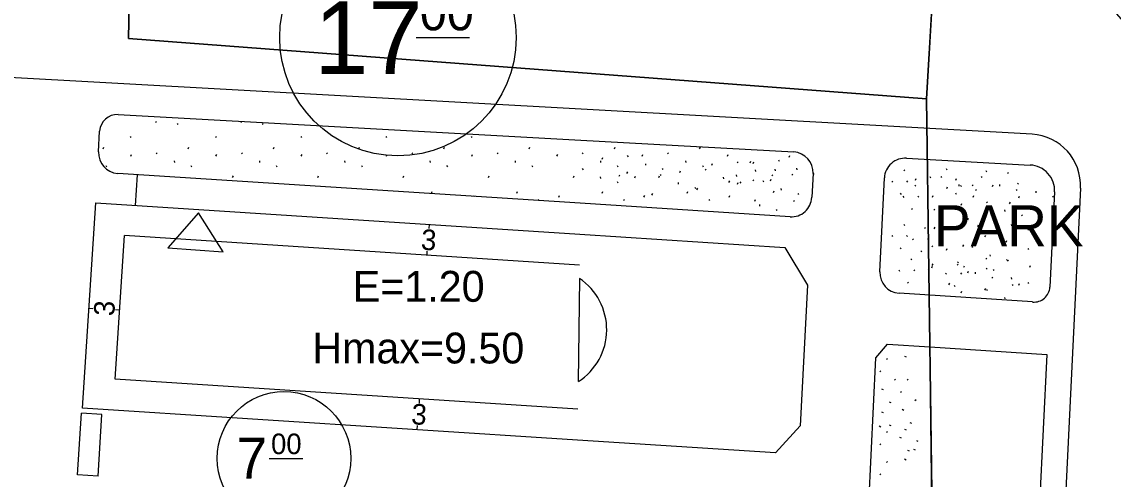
# Model space of a CAD drawing. Extents: x 419396 to 421519, y 4453567 to 4456767.
# Drawn here: x 421210.1 to 421316.3, y 4454782 to 4454826.5 of the extents above; entities that cross this region are included whole.
import ezdxf

# ---------------------------------------------------------------- set-up
doc = ezdxf.new("R2010")
doc.units = 0
for name, color, linetype in [('0_KADASTRO', 7, 'Continuous'), ('Level 16', 7, 'Continuous'), ('Level 20', 7, 'Continuous'), ('Level 28', 7, 'Continuous'), ('Level 29', 7, 'Continuous'), ('Level 30', 7, 'Continuous'), ('Level 32', 7, 'Continuous'), ('Level 41', 7, 'Continuous'), ('Level 5', 7, 'Continuous'), ('Level 53', 7, 'Continuous'), ('Level 58', 7, 'Continuous'), ('Level 59', 7, 'Continuous'), ('Level 62', 7, 'Continuous')]:
    doc.layers.add(name, color=color, linetype=linetype)

msp = doc.modelspace()

# ---------------------------------------------------------------- linework, layer by layer
at = {"layer": '0_KADASTRO'}
for points in [[(421137.98, 4454923.3), (421214.86, 4454919.45), (421262.85, 4454917.05), (421316.7, 4454915.64), (421312.35, 4454909.46), (421306.52, 4454893.75), (421298.93, 4454879.53), (421285.07, 4454880), (421282.36, 4454831.02), (421298.78, 4454830.11), (421298.12, 4454819), (421220.47, 4454824.89), (421221.51, 4454877.03), (421221.57, 4454879.85), (421203.67, 4454880.3), (421204.77, 4454912.41), (421155.31, 4454914.55), (421152.21, 4454911.69), (421151.19, 4454881.63), (421145.39, 4454881.78), (421142.95, 4454883.52), (421140.69, 4454887.48), (421139.91, 4454900.08)], [(421127.23, 4454779.24), (421128.91, 4454801.39), (421131.96, 4454828.83), (421129.84, 4454852.82), (421130.22, 4454865.45), (421131.1, 4454878.14), (421221.51, 4454877.03), (421220.47, 4454824.89), (421298.12, 4454819), (421298.8, 4454768.82), (421229.78, 4454772.84), (421167.18, 4454777.23)], [(421297.3, 4454718.68), (421298.33, 4454743.86), (421298.65, 4454753.52), (421298.8, 4454768.82), (421298.12, 4454819), (421299.79, 4454847.06), (421309.91, 4454834.93), (421332.63, 4454808.99), (421350.71, 4454801.96), (421374.76, 4454802.88), (421400.86, 4454807.28), (421429.39, 4454805.15), (421423.5, 4454722.17), (421393.26, 4454602.31), (421372.96, 4454614.59), (421362.83, 4454633.4), (421361.48, 4454641.58), (421342.8, 4454669.52), (421331.29, 4454695.38), (421310.81, 4454712.23)], [(421297.3, 4454718.68), (421298.33, 4454743.86), (421298.65, 4454753.52), (421298.8, 4454768.82), (421298.12, 4454819), (421299.79, 4454847.06), (421309.91, 4454834.93), (421332.63, 4454808.99), (421350.71, 4454801.96), (421374.76, 4454802.88), (421400.86, 4454807.28), (421429.39, 4454805.15), (421423.5, 4454722.17), (421393.26, 4454602.31), (421372.96, 4454614.59), (421362.83, 4454633.4), (421361.48, 4454641.58), (421342.8, 4454669.52), (421331.29, 4454695.38), (421310.81, 4454712.23)]]:
    msp.add_lwpolyline(points, close=True, dxfattribs=at)
at = {"layer": 'Level 16'}
for p, q in [((421227.29, 4454807.91), (421224.32, 4454804.52)), ((421229.7, 4454804.11), (421227.29, 4454807.91)), ((421224.32, 4454804.52), (421229.7, 4454804.11))]:
    msp.add_line(p, q, dxfattribs=at)
at = {"layer": 'Level 20'}
for p, q in [((421249.72, 4454806.79), (421249.69, 4454806.39)), ((421219.18, 4454791.73), (421220.09, 4454805.7)), ((421264.36, 4454802.84), (421220.09, 4454805.7)), ((421249.53, 4454803.8), (421249.55, 4454804.2)), ((421264.36, 4454802.84), (421264.36, 4454802.84)), ((421264.36, 4454802.84), (421264.36, 4454802.84)), ((421264.36, 4454802.84), (421264.36, 4454802.84)), ((421216.62, 4454798.66), (421217.02, 4454798.63)), ((421219.62, 4454798.46), (421219.22, 4454798.49)), ((421264.21, 4454788.82), (421219.18, 4454791.73)), ((421248.77, 4454789.82), (421248.75, 4454789.42)), ((421264.21, 4454788.82), (421264.21, 4454788.82)), ((421264.21, 4454788.82), (421264.21, 4454788.82)), ((421264.21, 4454788.82), (421264.21, 4454788.82)), ((421248.58, 4454786.83), (421248.6, 4454787.22))]:
    msp.add_line(p, q, dxfattribs=at)
at = {"layer": 'Level 28'}
for p, q in [((421219.48, 4454817.48), (421264.49, 4454814.98)), ((421217.56, 4454813.86), (421217.67, 4454815.86)), ((421264.49, 4454814.98), (421264.49, 4454814.98)), ((421264.49, 4454814.98), (421264.49, 4454814.98)), ((421264.49, 4454814.98), (421264.49, 4454814.98)), ((421264.42, 4454808.85), (421219.43, 4454811.75)), ((421221.32, 4454811.63), (421221.13, 4454808.64)), ((421215.99, 4454788.92), (421217.29, 4454808.88)), ((421264.42, 4454808.85), (421264.42, 4454808.85)), ((421264.42, 4454808.85), (421264.42, 4454808.85)), ((421264.42, 4454808.85), (421264.42, 4454808.85))]:
    msp.add_line(p, q, dxfattribs=at)
for centre, radius, start, end in [((421219.38, 4454815.77), 1.71, 86.8311, 176.8311), ((421219.56, 4454813.75), 2, 176.8311, 266.3111)]:
    msp.add_arc(centre, radius, start, end, dxfattribs=at)
at = {"layer": 'Level 29'}
for p, q in [((421217.29, 4454808.88), (421264.39, 4454805.85)), ((421264.39, 4454805.85), (421264.39, 4454805.85)), ((421264.39, 4454805.85), (421264.39, 4454805.85)), ((421264.39, 4454805.85), (421264.39, 4454805.85)), ((421298.45, 4454794.88), (421309.82, 4454794.15)), ((421309.82, 4454794.15), (421306.57, 4454727.03)), ((421264.18, 4454785.82), (421215.99, 4454788.92)), ((421264.18, 4454785.82), (421264.18, 4454785.82)), ((421264.18, 4454785.82), (421264.18, 4454785.82)), ((421264.18, 4454785.82), (421264.18, 4454785.82))]:
    msp.add_line(p, q, dxfattribs=at)
at = {"layer": 'Level 32'}
msp.add_lwpolyline([(421264.35, 4454801.54), (421264.24, 4454791.5)], dxfattribs=at)
msp.add_arc((421261.01, 4454796.56), 6, 302.6363, 56.1689, dxfattribs=at)
at = {"layer": 'Level 41'}
for p, q in [((421223.1, 4454816.8), (421223.17, 4454816.69)), ((421225.2, 4454816.61), (421225.27, 4454816.5)), ((421231.39, 4454816.8), (421231.46, 4454816.69)), ((421233.49, 4454816.61), (421233.56, 4454816.5)), ((421220.64, 4454815.35), (421220.71, 4454815.24)), ((421228.93, 4454815.35), (421229, 4454815.24)), ((421237.23, 4454815.35), (421237.3, 4454815.24)), ((421245.52, 4454815.35), (421245.59, 4454815.24)), ((421253.81, 4454815.35), (421253.88, 4454815.24)), ((421218, 4454814.15), (421218.07, 4454814.31)), ((421220.7, 4454813.43), (421220.77, 4454813.59)), ((421223.16, 4454813.77), (421223.23, 4454813.66)), ((421226.29, 4454814.15), (421226.36, 4454814.31)), ((421228.99, 4454813.43), (421229.06, 4454813.59)), ((421231.46, 4454813.77), (421231.53, 4454813.66)), ((421234.59, 4454814.15), (421234.66, 4454814.31)), ((421237.28, 4454813.43), (421237.36, 4454813.59)), ((421239.75, 4454813.77), (421239.82, 4454813.66)), ((421242.88, 4454814.15), (421242.95, 4454814.31)), ((421245.58, 4454813.43), (421245.65, 4454813.59)), ((421248.04, 4454813.77), (421248.11, 4454813.66)), ((421251.17, 4454814.15), (421251.24, 4454814.31)), ((421253.87, 4454813.43), (421253.94, 4454813.59)), ((421256.34, 4454813.77), (421256.41, 4454813.66)), ((421259.46, 4454814.15), (421259.54, 4454814.31)), ((421262.16, 4454813.43), (421262.24, 4454813.59)), ((421264.63, 4454813.77), (421264.7, 4454813.66)), ((421267.76, 4454814.15), (421267.83, 4454814.31)), ((421269.01, 4454813.49), (421269.08, 4454813.38)), ((421270.46, 4454813.43), (421270.53, 4454813.59)), ((421272.92, 4454813.77), (421272.99, 4454813.66)), ((421276.05, 4454814.15), (421276.12, 4454814.31)), ((421278.75, 4454813.43), (421278.82, 4454813.59)), ((421284.76, 4454813.33), (421284.83, 4454813.49)), ((421218.26, 4454812.51), (421218.33, 4454812.4)), ((421224.92, 4454812.98), (421224.94, 4454812.82)), ((421226.55, 4454812.51), (421226.62, 4454812.4)), ((421233.21, 4454812.98), (421233.23, 4454812.82)), ((421234.84, 4454812.51), (421234.91, 4454812.4)), ((421241.51, 4454812.98), (421241.53, 4454812.82)), ((421243.14, 4454812.51), (421243.21, 4454812.4)), ((421249.8, 4454812.98), (421249.82, 4454812.82)), ((421251.43, 4454812.51), (421251.5, 4454812.4)), ((421258.09, 4454812.98), (421258.11, 4454812.82)), ((421259.72, 4454812.51), (421259.79, 4454812.4)), ((421266.39, 4454812.98), (421266.4, 4454812.82)), ((421266.55, 4454813.15), (421266.62, 4454813.31)), ((421268.02, 4454812.51), (421268.09, 4454812.4)), ((421270.77, 4454812.7), (421270.79, 4454812.54)), ((421274.68, 4454812.98), (421274.7, 4454812.82)), ((421276.31, 4454812.51), (421276.38, 4454812.4)), ((421277.23, 4454812.55), (421277.3, 4454812.71)), ((421279.69, 4454812.89), (421279.76, 4454812.79)), ((421280.97, 4454812.79), (421281.04, 4454812.95)), ((421281.25, 4454812.71), (421281.32, 4454812.87)), ((421283.72, 4454813.06), (421283.79, 4454812.95)), ((421230.61, 4454811.37), (421230.68, 4454811.53)), ((421238.9, 4454811.37), (421238.97, 4454811.53)), ((421247.19, 4454811.37), (421247.27, 4454811.53)), ((421255.49, 4454811.37), (421255.56, 4454811.53)), ((421263.78, 4454811.37), (421263.85, 4454811.53)), ((421264.63, 4454812.22), (421264.7, 4454812.11)), ((421266.38, 4454811.43), (421266.4, 4454811.27)), ((421268.22, 4454811.47), (421268.29, 4454811.63)), ((421268.98, 4454811.75), (421269.05, 4454811.91)), ((421269.73, 4454811.31), (421269.81, 4454811.47)), ((421272.07, 4454811.37), (421272.14, 4454811.53)), ((421272.2, 4454811.66), (421272.27, 4454811.55)), ((421272.4, 4454812.23), (421272.47, 4454812.12)), ((421274.12, 4454811.83), (421274.19, 4454811.99)), ((421276.58, 4454812.18), (421276.65, 4454812.07)), ((421278.34, 4454811.39), (421278.36, 4454811.23)), ((421279.6, 4454811.61), (421279.62, 4454811.45)), ((421281.45, 4454812.1), (421281.47, 4454811.94)), ((421283.08, 4454811.63), (421283.15, 4454811.53)), ((421283.38, 4454812.16), (421283.4, 4454812)), ((421285.01, 4454811.69), (421285.08, 4454811.58)), ((421285.47, 4454812.27), (421285.49, 4454812.11)), ((421287.1, 4454811.8), (421287.17, 4454811.69)), ((421295.91, 4454812.09), (421295.98, 4454811.99)), ((421297.04, 4454811.11), (421297.11, 4454811.27)), ((421298.43, 4454811.44), (421298.5, 4454811.33)), ((421299.5, 4454811.46), (421299.57, 4454811.35)), ((421300.03, 4454812.22), (421300.1, 4454812.11)), ((421300.98, 4454811.11), (421301.05, 4454811.27)), ((421303.45, 4454811.46), (421303.52, 4454811.35)), ((421303.89, 4454812.03), (421303.96, 4454811.92)), ((421305.99, 4454811.84), (421306.06, 4454811.73)), ((421268.01, 4454810.96), (421268.08, 4454810.85)), ((421273.96, 4454810.87), (421273.97, 4454810.71)), ((421275.59, 4454810.4), (421275.66, 4454810.29)), ((421275.79, 4454810.16), (421275.86, 4454810.32)), ((421278.9, 4454810.87), (421278.97, 4454811.03)), ((421279.74, 4454810.72), (421279.81, 4454810.88)), ((421279.97, 4454810.92), (421280.04, 4454810.81)), ((421281.23, 4454811.14), (421281.3, 4454811.04)), ((421282.2, 4454811.06), (421282.27, 4454810.95)), ((421282.93, 4454811.04), (421283, 4454811.2)), ((421283.96, 4454810.27), (421283.98, 4454810.11)), ((421294.74, 4454811), (421294.81, 4454810.89)), ((421296.19, 4454811.02), (421296.27, 4454810.91)), ((421297, 4454810.62), (421297.07, 4454810.51)), ((421300.09, 4454810.3), (421300.16, 4454810.46)), ((421301.26, 4454810.67), (421301.28, 4454810.51)), ((421301.44, 4454810.58), (421301.51, 4454810.47)), ((421302.55, 4454810.64), (421302.62, 4454810.53)), ((421302.89, 4454810.2), (421302.96, 4454810.09)), ((421304.53, 4454810.48), (421304.6, 4454810.64)), ((421305.21, 4454810.67), (421305.22, 4454810.51)), ((421306.84, 4454810.2), (421306.91, 4454810.09)), ((421306.99, 4454810.82), (421307.07, 4454810.71)), ((421249.97, 4454809.84), (421250.04, 4454810)), ((421254.09, 4454809.52), (421254.12, 4454809.59)), ((421258.26, 4454809.84), (421258.33, 4454810)), ((421260.35, 4454809.22), (421260.42, 4454809.11)), ((421262.34, 4454809.43), (421262.41, 4454809.59)), ((421266.55, 4454809.84), (421266.62, 4454810)), ((421268.65, 4454809.22), (421268.72, 4454809.11)), ((421270.63, 4454809.43), (421270.71, 4454809.59)), ((421271.41, 4454809.64), (421271.48, 4454809.8)), ((421274.84, 4454809.84), (421274.91, 4454810)), ((421276.94, 4454809.22), (421277.01, 4454809.11)), ((421278.93, 4454809.43), (421279, 4454809.59)), ((421281.41, 4454809.04), (421281.48, 4454809.2)), ((421283.23, 4454809.9), (421283.3, 4454810.06)), ((421285.18, 4454809.13), (421285.25, 4454809.03)), ((421285.59, 4454809.8), (421285.66, 4454809.69)), ((421295.56, 4454809.82), (421295.64, 4454809.71)), ((421295.83, 4454809.53), (421295.9, 4454809.42)), ((421297.29, 4454809.54), (421297.36, 4454809.43)), ((421298.71, 4454809.44), (421298.78, 4454809.6)), ((421300.95, 4454809.86), (421301.02, 4454809.75)), ((421302.66, 4454809.44), (421302.73, 4454809.6)), ((421307.09, 4454809.38), (421307.16, 4454809.54)), ((421308.75, 4454810.03), (421308.77, 4454809.87)), ((421310.38, 4454809.56), (421310.45, 4454809.45)), ((421281.86, 4454808.72), (421281.88, 4454808.56)), ((421283.49, 4454808.25), (421283.56, 4454808.15)), ((421296.66, 4454808.34), (421296.73, 4454808.23)), ((421298.82, 4454808.27), (421298.89, 4454808.17)), ((421301.49, 4454808.66), (421301.57, 4454808.82)), ((421303.96, 4454809), (421304.03, 4454808.89)), ((421305.72, 4454808.21), (421305.73, 4454808.05)), ((421306.2, 4454808.8), (421306.28, 4454808.96)), ((421302.14, 4454807.25), (421302.21, 4454807.41)), ((421304.6, 4454807.59), (421304.67, 4454807.49)), ((421307.35, 4454807.74), (421307.42, 4454807.63)), ((421295.91, 4454806.81), (421295.98, 4454806.7)), ((421297.92, 4454806.49), (421297.99, 4454806.39)), ((421298.88, 4454806.35), (421298.95, 4454806.51)), ((421301.34, 4454806.7), (421301.41, 4454806.59)), ((421303.11, 4454806.6), (421303.18, 4454806.76)), ((421306.36, 4454806.8), (421306.38, 4454806.64)), ((421307.99, 4454806.33), (421308.06, 4454806.22)), ((421294.74, 4454805.72), (421294.81, 4454805.61)), ((421296.19, 4454805.73), (421296.27, 4454805.63)), ((421296.75, 4454805.4), (421296.82, 4454805.29)), ((421298.21, 4454805.42), (421298.28, 4454805.31)), ((421303.81, 4454805.57), (421303.88, 4454805.73)), ((421305.88, 4454805.07), (421305.95, 4454805.23)), ((421295.56, 4454804.53), (421295.64, 4454804.43)), ((421297.58, 4454804.22), (421297.65, 4454804.11)), ((421298.63, 4454804.72), (421298.7, 4454804.61)), ((421300.07, 4454804.3), (421300.14, 4454804.46)), ((421301.67, 4454804.66), (421301.74, 4454804.82)), ((421302.53, 4454804.64), (421302.6, 4454804.54)), ((421304.29, 4454803.85), (421304.31, 4454803.69)), ((421307.98, 4454804.45), (421308.05, 4454804.34)), ((421296.6, 4454803.46), (421296.68, 4454803.36)), ((421298.68, 4454802.8), (421298.76, 4454802.96)), ((421301.1, 4454802.93), (421301.17, 4454802.82)), ((421301.15, 4454803.14), (421301.22, 4454803.04)), ((421301.74, 4454802.62), (421301.81, 4454802.78)), ((421303.89, 4454803.52), (421303.96, 4454803.41)), ((421305.92, 4454803.38), (421305.99, 4454803.28)), ((421305.99, 4454803.33), (421306.06, 4454803.22)), ((421308.18, 4454802.65), (421308.25, 4454802.81)), ((421295.43, 4454802.37), (421295.5, 4454802.26)), ((421296.89, 4454802.39), (421296.96, 4454802.28)), ((421298.28, 4454802.44), (421298.35, 4454802.34)), ((421298.63, 4454802.58), (421298.7, 4454802.74)), ((421299.98, 4454802.05), (421300.05, 4454801.94)), ((421301.44, 4454802.07), (421301.51, 4454801.96)), ((421302.14, 4454802.07), (421302.21, 4454802.23)), ((421302.85, 4454802.14), (421302.87, 4454801.98)), ((421303.93, 4454802.54), (421304.01, 4454802.43)), ((421304.6, 4454802.41), (421304.67, 4454802.3)), ((421296.26, 4454801.19), (421296.33, 4454801.08)), ((421300.3, 4454800.91), (421300.38, 4454801.07)), ((421300.81, 4454800.87), (421300.88, 4454800.76)), ((421304.48, 4454801.67), (421304.55, 4454801.56)), ((421306.36, 4454801.62), (421306.38, 4454801.46)), ((421306.46, 4454800.96), (421306.53, 4454800.85)), ((421307.09, 4454800.87), (421307.16, 4454801.03)), ((421307.99, 4454801.15), (421308.06, 4454801.04)), ((421301.49, 4454800.15), (421301.57, 4454800.31)), ((421303.81, 4454800.39), (421303.88, 4454800.55)), ((421303.96, 4454800.49), (421304.03, 4454800.38)), ((421305.72, 4454799.7), (421305.73, 4454799.54)), ((421294.34, 4454793.72), (421294.24, 4454793.65)), ((421295.99, 4454793.98), (421296.15, 4454793.91)), ((421293.69, 4454792.51), (421293.58, 4454792.44)), ((421295.1, 4454791.71), (421295, 4454791.64)), ((421296.34, 4454791.73), (421296.23, 4454791.66)), ((421293.74, 4454790.8), (421293.9, 4454790.73)), ((421295.68, 4454790.52), (421295.58, 4454790.45)), ((421294.5, 4454789.53), (421294.66, 4454789.46)), ((421297.1, 4454789.72), (421296.99, 4454789.65)), ((421293.74, 4454788.57), (421293.9, 4454788.5)), ((421295.74, 4454788.81), (421295.9, 4454788.74)), ((421293.51, 4454787.19), (421293.67, 4454787.12)), ((421294.5, 4454787.3), (421294.66, 4454787.23)), ((421295.99, 4454786.89), (421296.15, 4454786.82)), ((421296.5, 4454787.54), (421296.66, 4454787.47)), ((421294.34, 4454786.63), (421294.24, 4454786.56)), ((421295.5, 4454786.1), (421295.66, 4454786.03)), ((421297.14, 4454785.78), (421297.29, 4454785.71)), ((421293.69, 4454785.42), (421293.58, 4454785.34)), ((421296.26, 4454784.83), (421296.42, 4454784.76)), ((421296.86, 4454784.93), (421297.02, 4454784.86)), ((421294.34, 4454783.72), (421294.24, 4454783.65)), ((421295.99, 4454783.98), (421296.15, 4454783.91)), ((421293.69, 4454782.51), (421293.58, 4454782.43))]:
    msp.add_line(p, q, dxfattribs=at)
at = {"layer": 'Level 5'}
msp.add_line((421298.8, 4454768.82), (421298.47, 4454792.88), dxfattribs=at)
at = {"layer": 'Level 53'}
for p, q in [((421215.53, 4454782.43), (421215.9, 4454788.42)), ((421217.9, 4454788.29), (421215.9, 4454788.42)), ((421217.53, 4454782.31), (421217.9, 4454788.29)), ((421217.53, 4454782.31), (421215.53, 4454782.43))]:
    msp.add_line(p, q, dxfattribs=at)
at = {"layer": 'Level 58'}
for p, q in [((421248.46, 4454824.96), (421253.65, 4454824.96)), ((421234.15, 4454784.04), (421237.45, 4454784.04))]:
    msp.add_line(p, q, dxfattribs=at)
for centre, radius in [((421246.69, 4454824.96), 11.5), ((421235.6, 4454784.04), 6.5)]:
    msp.add_circle(centre, radius, dxfattribs=at)
at = {"layer": 'Level 59'}
for p, q in [((421264.49, 4454814.98), (421285.2, 4454813.84)), ((421296.18, 4454813.23), (421308.21, 4454812.56)), ((421287.09, 4454811.74), (421286.97, 4454809.43)), ((421293.58, 4454802.18), (421294.02, 4454811.33)), ((421310.58, 4454809.95), (421310.13, 4454800.69)), ((421284.85, 4454807.53), (421264.42, 4454808.85)), ((421264.39, 4454805.85), (421284.34, 4454804.56)), ((421284.34, 4454804.56), (421286.53, 4454800.89)), ((421286.53, 4454800.89), (421285.83, 4454787.2)), ((421308.44, 4454799.25), (421295.45, 4454800.09)), ((421293.18, 4454793.83), (421294.33, 4454795.13)), ((421294.33, 4454795.13), (421298.45, 4454794.87)), ((421298.45, 4454794.88), (421298.8, 4454768.82)), ((421292.01, 4454769.45), (421293.18, 4454793.83)), ((421285.83, 4454787.2), (421283.44, 4454784.58)), ((421283.44, 4454784.58), (421264.18, 4454785.82))]:
    msp.add_line(p, q, dxfattribs=at)
for centre, radius, start, end in [((421285.09, 4454811.84), 2, 357.0712, 86.8304), ((421296.02, 4454811.23), 2, 85.4452, 177.2515), ((421308.09, 4454810.07), 2.5, 357.2286, 87.3185), ((421284.97, 4454809.53), 2, 266.3113, 357.0712), ((421295.58, 4454802.09), 2, 177.2515, 266.2851), ((421308.58, 4454800.8), 1.56, 264.8935, 355.9014), ((421308.58, 4454800.8), 1.56, 266.2833, 266.5659)]:
    msp.add_arc(centre, radius, start, end, dxfattribs=at)
at = {"layer": 'Level 62'}
for p, q in [((421264.52, 4454817.99), (421140.31, 4454824.87)), ((421264.52, 4454817.99), (421264.52, 4454817.99)), ((421264.52, 4454817.99), (421264.52, 4454817.99)), ((421264.52, 4454817.99), (421264.52, 4454817.99)), ((421308.39, 4454815.56), (421264.52, 4454817.99)), ((421313.1, 4454810.33), (421308.27, 4454710.53))]:
    msp.add_line(p, q, dxfattribs=at)
msp.add_arc((421308.11, 4454810.57), 5, 357.2286, 86.8311, dxfattribs=at)

# ---------------------------------------------------------------- texts
at = {"layer": 'Level 20'}
for rotation, p in [(356.3111, (421248.89, 4454804.34)), (86.2833, (421219.08, 4454797.83)), (356.3111, (421247.95, 4454787.37))]:
    msp.add_text('3', height=2, rotation=rotation, dxfattribs=at).set_placement(p)
at = {"layer": 'Level 30'}
for s, p in [('E=1.20', (421242.3, 4454799.27)), ('Hmax=9.50', (421238.36, 4454793.27))]:
    msp.add_text(s, height=3, dxfattribs=at).set_placement(p)
at = {"layer": 'Level 41'}
msp.add_text('PARK', height=4, dxfattribs=at).set_placement((421298.84, 4454804.65))
at = {"layer": 'Level 58'}
for s, height, p in [('17', 7.071, (421238.56, 4454821.43)), ('00', 3.536, (421248.82, 4454825.67)), ('7', 4, (421231, 4454782.05)), ('00', 1.998, (421234.35, 4454784.45))]:
    msp.add_text(s, height=height, dxfattribs=at).set_placement(p)

doc.saveas('drawing.dxf')
